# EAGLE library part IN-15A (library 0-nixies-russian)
IN-15A: medium symbol topview nixie tube
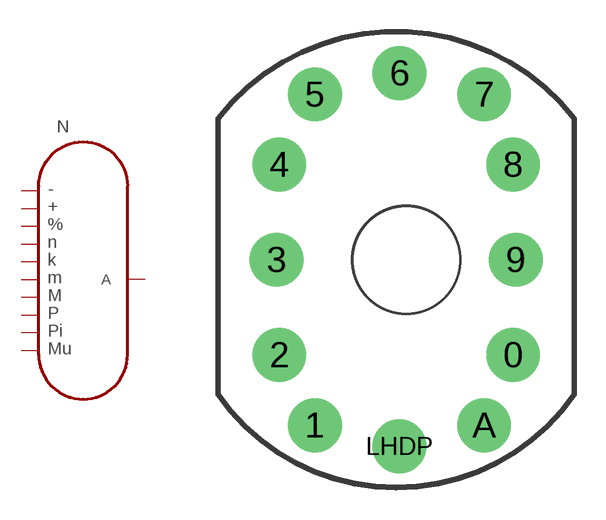
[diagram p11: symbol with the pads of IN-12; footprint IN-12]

Designator prefix N

## IN-15A  [IN-12]
0  P$10
1  P$4
2  P$3
3  P$9
4  P$5
5  P$7
6  P$6
7  P$2
8  P$1
9  P$8
A  A

## Footprint IN-12 (pad centres in mm)
May be used with socket: SK-136
drill 1.1 pad 2.54 round: 0 5.048,-4.5; 1 -4.317,-7.817; 2 -6,-4.5; 3 -6.127,0; 4 -6,4.5; 5 -4.317,7.817; 6 -0.318,8.818; 7 3.683,7.817; 8 5.048,4.5; 9 5.175,0; A 3.683,-7.817; LHDP -0.318,-8.818
hole 5 at 0,0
